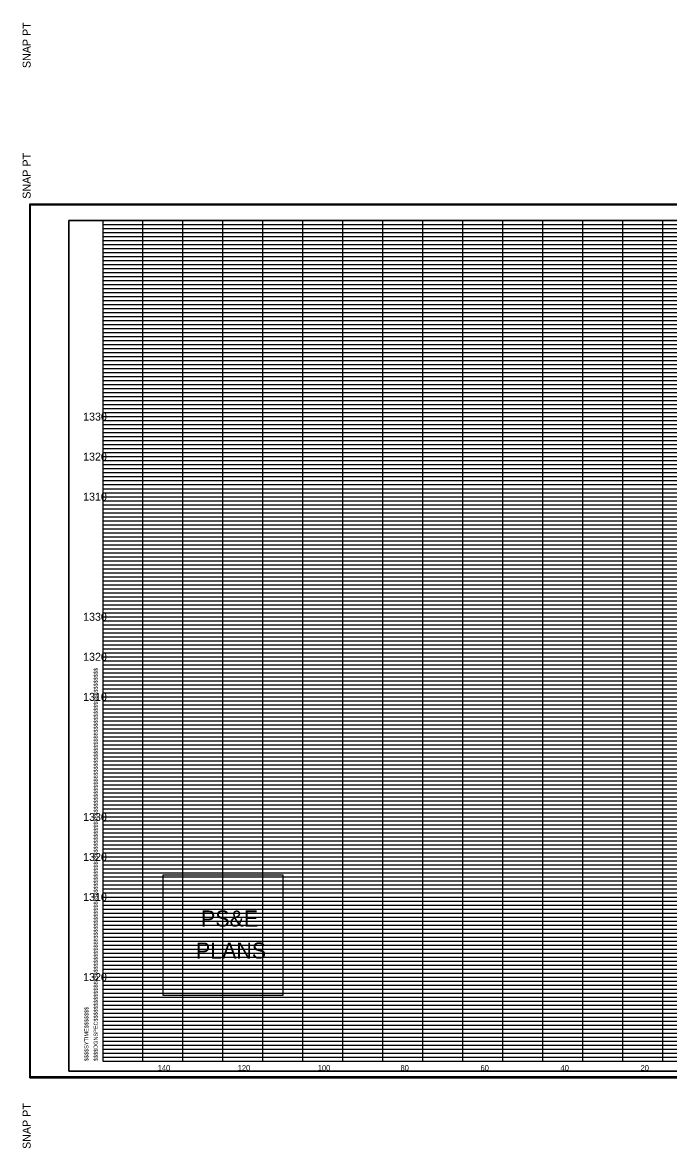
# Model space of a CAD drawing. Extents: x 980 to 1324, y 978 to 1767.
# Drawn here: x 979.9 to 1141.4, y 978.2 to 1259.4 of the extents above; entities that cross this region are included whole.
import ezdxf

# ---------------------------------------------------------------- set-up
doc = ezdxf.new("R2010")
doc.units = 0
for name, color, linetype in [('DESIGN - SHEET - Corner Text', 7, 'Continuous'), ('DESIGN - SHEET - Light Grid', 7, 'Continuous'), ('DESIGN - SHEET - Linework', 7, 'Continuous'), ('DESIGN - SHEET - Plot Shape', 7, 'Continuous'), ('DESIGN - TYPICAL - Text', 7, 'Continuous')]:
    doc.layers.add(name, color=color, linetype=linetype)

# ---------------------------------------------------------------- blocks, each defined once
blk = doc.blocks.new('XSTSHT')
at = {"layer": 'DESIGN - SHEET - Light Grid'}
for p, q in [((0, 20.9), (8, 20.9)), ((8, 20.9), (16, 20.9)), ((0, 20.8), (8, 20.8)), ((0, 20.7), (8, 20.7)), ((0, 20.6), (8, 20.6)), ((8, 20.8), (16, 20.8)), ((8, 20.7), (16, 20.7)), ((8, 20.6), (16, 20.6)), ((0, 20.5), (8, 20.5)), ((0, 20.4), (8, 20.4)), ((0, 20.3), (8, 20.3)), ((8, 20.5), (16, 20.5)), ((8, 20.4), (16, 20.4)), ((8, 20.3), (16, 20.3)), ((0, 20.2), (8, 20.2)), ((0, 20.1), (8, 20.1)), ((8, 20.2), (16, 20.2)), ((8, 20.1), (16, 20.1)), ((0, 19.9), (8, 19.9)), ((0, 19.8), (8, 19.8)), ((0, 19.7), (8, 19.7)), ((8, 19.9), (16, 19.9)), ((8, 19.8), (16, 19.8)), ((8, 19.7), (16, 19.7)), ((0, 19.6), (8, 19.6)), ((0, 19.5), (8, 19.5)), ((8, 19.6), (16, 19.6)), ((8, 19.5), (16, 19.5)), ((0, 19.4), (8, 19.4)), ((0, 19.3), (8, 19.3)), ((0, 19.2), (8, 19.2)), ((8, 19.4), (16, 19.4)), ((8, 19.3), (16, 19.3)), ((8, 19.2), (16, 19.2)), ((0, 19.1), (8, 19.1)), ((0, 18.9), (8, 18.9)), ((8, 19.1), (16, 19.1)), ((8, 18.9), (16, 18.9)), ((0, 18.8), (8, 18.8)), ((0, 18.7), (8, 18.7)), ((0, 18.6), (8, 18.6)), ((8, 18.8), (16, 18.8)), ((8, 18.7), (16, 18.7)), ((8, 18.6), (16, 18.6)), ((0, 18.5), (8, 18.5)), ((0, 18.4), (8, 18.4)), ((0, 18.3), (8, 18.3)), ((8, 18.5), (16, 18.5)), ((8, 18.4), (16, 18.4)), ((8, 18.3), (16, 18.3)), ((0, 18.2), (8, 18.2)), ((0, 18.1), (8, 18.1)), ((8, 18.2), (16, 18.2)), ((8, 18.1), (16, 18.1)), ((0, 17.9), (8, 17.9)), ((0, 17.8), (8, 17.8)), ((8, 17.9), (16, 17.9)), ((8, 17.8), (16, 17.8)), ((0, 17.7), (8, 17.7)), ((0, 17.6), (8, 17.6)), ((0, 17.5), (8, 17.5)), ((8, 17.7), (16, 17.7)), ((8, 17.6), (16, 17.6)), ((8, 17.5), (16, 17.5)), ((0, 17.4), (8, 17.4)), ((0, 17.3), (8, 17.3)), ((0, 17.2), (8, 17.2)), ((8, 17.4), (16, 17.4)), ((8, 17.3), (16, 17.3)), ((8, 17.2), (16, 17.2)), ((0, 17.1), (8, 17.1)), ((0, 16.9), (8, 16.9)), ((8, 17.1), (16, 17.1)), ((8, 16.9), (16, 16.9)), ((0, 16.8), (8, 16.8)), ((0, 16.7), (8, 16.7)), ((0, 16.6), (8, 16.6)), ((8, 16.8), (16, 16.8)), ((8, 16.7), (16, 16.7)), ((8, 16.6), (16, 16.6)), ((0, 16.5), (8, 16.5)), ((0, 16.4), (8, 16.4)), ((8, 16.5), (16, 16.5)), ((8, 16.4), (16, 16.4)), ((0, 16.3), (8, 16.3)), ((0, 16.2), (8, 16.2)), ((0, 16.1), (8, 16.1)), ((8, 16.3), (16, 16.3)), ((8, 16.2), (16, 16.2)), ((8, 16.1), (16, 16.1)), ((0, 15.9), (8, 15.9)), ((0, 15.8), (8, 15.8)), ((8, 15.9), (16, 15.9)), ((8, 15.8), (16, 15.8)), ((0, 15.7), (8, 15.7)), ((0, 15.6), (8, 15.6)), ((0, 15.5), (8, 15.5)), ((8, 15.7), (16, 15.7)), ((8, 15.6), (16, 15.6)), ((8, 15.5), (16, 15.5)), ((0, 15.4), (8, 15.4)), ((0, 15.3), (8, 15.3)), ((0, 15.2), (8, 15.2)), ((8, 15.4), (16, 15.4)), ((8, 15.3), (16, 15.3)), ((8, 15.2), (16, 15.2)), ((0, 15.1), (8, 15.1)), ((8, 15.1), (16, 15.1)), ((0, 14.9), (8, 14.9)), ((0, 14.8), (8, 14.8)), ((0, 14.7), (8, 14.7)), ((8, 14.9), (16, 14.9)), ((8, 14.8), (16, 14.8)), ((8, 14.7), (16, 14.7)), ((0, 14.6), (8, 14.6)), ((0, 14.5), (8, 14.5)), ((0, 14.4), (8, 14.4)), ((8, 14.6), (16, 14.6)), ((8, 14.5), (16, 14.5)), ((8, 14.4), (16, 14.4)), ((0, 14.3), (8, 14.3)), ((0, 14.2), (8, 14.2)), ((0, 14.1), (8, 14.1)), ((8, 14.3), (16, 14.3)), ((8, 14.2), (16, 14.2)), ((8, 14.1), (16, 14.1)), ((0, 13.9), (8, 13.9)), ((0, 13.8), (8, 13.8)), ((8, 13.9), (16, 13.9)), ((8, 13.8), (16, 13.8)), ((0, 13.7), (8, 13.7)), ((0, 13.6), (8, 13.6)), ((8, 13.7), (16, 13.7)), ((8, 13.6), (16, 13.6)), ((0, 13.5), (8, 13.5)), ((0, 13.4), (8, 13.4)), ((0, 13.3), (8, 13.3)), ((8, 13.5), (16, 13.5)), ((8, 13.4), (16, 13.4)), ((8, 13.3), (16, 13.3)), ((0, 13.2), (8, 13.2)), ((0, 13.1), (8, 13.1)), ((8, 13.2), (16, 13.2)), ((8, 13.1), (16, 13.1)), ((0, 12.9), (8, 12.9)), ((0, 12.8), (8, 12.8)), ((0, 12.7), (8, 12.7)), ((8, 12.9), (16, 12.9)), ((8, 12.8), (16, 12.8)), ((8, 12.7), (16, 12.7)), ((0, 12.6), (8, 12.6)), ((0, 12.5), (8, 12.5)), ((0, 12.4), (8, 12.4)), ((8, 12.6), (16, 12.6)), ((8, 12.5), (16, 12.5)), ((8, 12.4), (16, 12.4)), ((0, 12.3), (8, 12.3)), ((0, 12.2), (8, 12.2)), ((0, 12.1), (8, 12.1)), ((8, 12.3), (16, 12.3)), ((8, 12.2), (16, 12.2)), ((8, 12.1), (16, 12.1)), ((0, 11.9), (8, 11.9)), ((8, 11.9), (16, 11.9)), ((0, 11.8), (8, 11.8)), ((0, 11.7), (8, 11.7)), ((0, 11.6), (8, 11.6)), ((8, 11.8), (16, 11.8)), ((8, 11.7), (16, 11.7)), ((8, 11.6), (16, 11.6)), ((0, 11.5), (8, 11.5)), ((0, 11.4), (8, 11.4)), ((0, 11.3), (8, 11.3)), ((8, 11.5), (16, 11.5)), ((8, 11.4), (16, 11.4)), ((8, 11.3), (16, 11.3)), ((0, 11.2), (8, 11.2)), ((0, 11.1), (8, 11.1)), ((8, 11.2), (16, 11.2)), ((8, 11.1), (16, 11.1)), ((0, 10.9), (8, 10.9)), ((0, 10.8), (8, 10.8)), ((0, 10.7), (8, 10.7)), ((8, 10.9), (16, 10.9)), ((8, 10.8), (16, 10.8)), ((8, 10.7), (16, 10.7)), ((0, 10.6), (8, 10.6)), ((0, 10.5), (8, 10.5)), ((8, 10.6), (16, 10.6)), ((8, 10.5), (16, 10.5)), ((0, 10.4), (8, 10.4)), ((0, 10.3), (8, 10.3)), ((0, 10.2), (8, 10.2)), ((8, 10.4), (16, 10.4)), ((8, 10.3), (16, 10.3)), ((8, 10.2), (16, 10.2)), ((0, 10.1), (8, 10.1)), ((0, 9.9), (8, 9.9)), ((8, 10.1), (16, 10.1)), ((8, 9.9), (16, 9.9)), ((0, 9.8), (8, 9.8)), ((0, 9.7), (8, 9.7)), ((0, 9.6), (8, 9.6)), ((8, 9.8), (16, 9.8)), ((8, 9.7), (16, 9.7)), ((8, 9.6), (16, 9.6)), ((0, 9.5), (8, 9.5)), ((0, 9.4), (8, 9.4)), ((0, 9.3), (8, 9.3)), ((8, 9.5), (16, 9.5)), ((8, 9.4), (16, 9.4)), ((8, 9.3), (16, 9.3)), ((0, 9.2), (8, 9.2)), ((0, 9.1), (8, 9.1)), ((8, 9.2), (16, 9.2)), ((8, 9.1), (16, 9.1)), ((0, 8.9), (8, 8.9)), ((0, 8.8), (8, 8.8)), ((8, 8.9), (16, 8.9)), ((8, 8.8), (16, 8.8)), ((0, 8.7), (8, 8.7)), ((0, 8.6), (8, 8.6)), ((0, 8.5), (8, 8.5)), ((8, 8.7), (16, 8.7)), ((8, 8.6), (16, 8.6)), ((8, 8.5), (16, 8.5)), ((0, 8.4), (8, 8.4)), ((0, 8.3), (8, 8.3)), ((0, 8.2), (8, 8.2)), ((8, 8.4), (16, 8.4)), ((8, 8.3), (16, 8.3)), ((8, 8.2), (16, 8.2)), ((0, 8.1), (8, 8.1)), ((0, 7.9), (8, 7.9)), ((8, 8.1), (16, 8.1)), ((8, 7.9), (16, 7.9)), ((0, 7.8), (8, 7.8)), ((0, 7.7), (8, 7.7)), ((0, 7.6), (8, 7.6)), ((8, 7.8), (16, 7.8)), ((8, 7.7), (16, 7.7)), ((8, 7.6), (16, 7.6)), ((0, 7.5), (8, 7.5)), ((0, 7.4), (8, 7.4)), ((8, 7.5), (16, 7.5)), ((8, 7.4), (16, 7.4)), ((0, 7.3), (8, 7.3)), ((0, 7.2), (8, 7.2)), ((0, 7.1), (8, 7.1)), ((8, 7.3), (16, 7.3)), ((8, 7.2), (16, 7.2)), ((8, 7.1), (16, 7.1)), ((0, 6.9), (8, 6.9)), ((0, 6.8), (8, 6.8)), ((8, 6.9), (16, 6.9)), ((8, 6.8), (16, 6.8)), ((0, 6.7), (8, 6.7)), ((0, 6.6), (8, 6.6)), ((0, 6.5), (8, 6.5)), ((8, 6.7), (16, 6.7)), ((8, 6.6), (16, 6.6)), ((8, 6.5), (16, 6.5)), ((0, 6.4), (8, 6.4)), ((0, 6.3), (8, 6.3)), ((0, 6.2), (8, 6.2)), ((8, 6.4), (16, 6.4)), ((8, 6.3), (16, 6.3)), ((8, 6.2), (16, 6.2)), ((0, 6.1), (8, 6.1)), ((8, 6.1), (16, 6.1)), ((0, 5.9), (8, 5.9)), ((0, 5.8), (8, 5.8)), ((0, 5.7), (8, 5.7)), ((8, 5.9), (16, 5.9)), ((8, 5.8), (16, 5.8)), ((8, 5.7), (16, 5.7)), ((0, 5.6), (8, 5.6)), ((0, 5.5), (8, 5.5)), ((0, 5.4), (8, 5.4)), ((8, 5.6), (16, 5.6)), ((8, 5.5), (16, 5.5)), ((8, 5.4), (16, 5.4)), ((0, 5.3), (8, 5.3)), ((0, 5.2), (8, 5.2)), ((0, 5.1), (8, 5.1)), ((8, 5.3), (16, 5.3)), ((8, 5.2), (16, 5.2)), ((8, 5.1), (16, 5.1)), ((0, 4.9), (8, 4.9)), ((0, 4.8), (8, 4.8)), ((8, 4.9), (16, 4.9)), ((8, 4.8), (16, 4.8)), ((0, 4.7), (8, 4.7)), ((0, 4.6), (8, 4.6)), ((8, 4.7), (16, 4.7)), ((8, 4.6), (16, 4.6)), ((0, 4.5), (8, 4.5)), ((0, 4.4), (8, 4.4)), ((0, 4.3), (8, 4.3)), ((8, 4.5), (16, 4.5)), ((8, 4.4), (16, 4.4)), ((8, 4.3), (16, 4.3)), ((0, 4.2), (8, 4.2)), ((0, 4.1), (8, 4.1)), ((8, 4.2), (16, 4.2)), ((8, 4.1), (16, 4.1)), ((0, 3.9), (8, 3.9)), ((0, 3.8), (8, 3.8)), ((0, 3.7), (8, 3.7)), ((8, 3.9), (16, 3.9)), ((8, 3.8), (16, 3.8)), ((8, 3.7), (16, 3.7)), ((0, 3.6), (8, 3.6)), ((0, 3.5), (8, 3.5)), ((0, 3.4), (8, 3.4)), ((8, 3.6), (16, 3.6)), ((8, 3.5), (16, 3.5)), ((8, 3.4), (16, 3.4)), ((0, 3.3), (8, 3.3)), ((0, 3.2), (8, 3.2)), ((0, 3.1), (8, 3.1)), ((8, 3.3), (16, 3.3)), ((8, 3.2), (16, 3.2)), ((8, 3.1), (16, 3.1)), ((0, 2.9), (8, 2.9)), ((8, 2.9), (16, 2.9)), ((0, 2.8), (8, 2.8)), ((0, 2.7), (8, 2.7)), ((0, 2.6), (8, 2.6)), ((8, 2.8), (16, 2.8)), ((8, 2.7), (16, 2.7)), ((8, 2.6), (16, 2.6)), ((0, 2.5), (8, 2.5)), ((0, 2.4), (8, 2.4)), ((0, 2.3), (8, 2.3)), ((8, 2.5), (16, 2.5)), ((8, 2.4), (16, 2.4)), ((8, 2.3), (16, 2.3)), ((0, 2.2), (8, 2.2)), ((0, 2.1), (8, 2.1)), ((8, 2.2), (16, 2.2)), ((8, 2.1), (16, 2.1)), ((0, 1.9), (8, 1.9)), ((0, 1.8), (8, 1.8)), ((0, 1.7), (8, 1.7)), ((8, 1.9), (16, 1.9)), ((8, 1.8), (16, 1.8)), ((8, 1.7), (16, 1.7)), ((0, 1.6), (8, 1.6)), ((0, 1.5), (8, 1.5)), ((8, 1.6), (16, 1.6)), ((8, 1.5), (16, 1.5)), ((0, 1.4), (8, 1.4)), ((0, 1.3), (8, 1.3)), ((0, 1.2), (8, 1.2)), ((8, 1.4), (16, 1.4)), ((8, 1.3), (16, 1.3)), ((8, 1.2), (16, 1.2)), ((0, 1.1), (8, 1.1)), ((0, 0.9), (8, 0.9)), ((8, 1.1), (16, 1.1)), ((8, 0.9), (16, 0.9)), ((0, 0.8), (8, 0.8)), ((0, 0.7), (8, 0.7)), ((0, 0.6), (8, 0.6)), ((8, 0.8), (16, 0.8)), ((8, 0.7), (16, 0.7)), ((8, 0.6), (16, 0.6)), ((0, 0.5), (8, 0.5)), ((0, 0.4), (8, 0.4)), ((0, 0.3), (8, 0.3)), ((8, 0.5), (16, 0.5)), ((8, 0.4), (16, 0.4)), ((8, 0.3), (16, 0.3)), ((0, 0.2), (8, 0.2)), ((0, 0.1), (8, 0.1)), ((8, 0.2), (16, 0.2)), ((8, 0.1), (16, 0.1))]:
    blk.add_line(p, q, dxfattribs=at)
at = {"layer": 'DESIGN - SHEET - Linework'}
for p, q in [((-1.823, -0.414), (-1.823, 21.414)), ((-1.823, 21.414), (32.217, 21.414)), ((1, 0), (1, 21)), ((2, 0), (2, 21)), ((3, 0), (3, 21)), ((4, 0), (4, 21)), ((5, 0), (5, 21)), ((6, 0), (6, 21)), ((7, 0), (7, 21)), ((8, 0), (8, 21)), ((9, 0), (9, 21)), ((10, 0), (10, 21)), ((11, 0), (11, 21)), ((12, 0), (12, 21)), ((13, 0), (13, 21)), ((14, 0), (14, 21)), ((0, 20), (28, 20)), ((0, 19), (32, 19)), ((0, 18), (32, 18)), ((0, 17), (32, 17)), ((0, 16), (32, 16)), ((0, 15), (32, 15)), ((0, 14), (32, 14)), ((0, 13), (32, 13)), ((0, 12), (32, 12)), ((0, 11), (32, 11)), ((0, 10), (32, 10)), ((0, 9), (32, 9)), ((0, 8), (32, 8)), ((0, 7), (32, 7)), ((0, 6), (32, 6)), ((0, 5), (32, 5)), ((0, 4), (32, 4)), ((0, 3), (32, 3)), ((0, 2), (32, 2)), ((0, 1), (32, 1)), ((-1.823, -0.414), (32.217, -0.414))]:
    blk.add_line(p, q, dxfattribs=at)
blk.add_lwpolyline([(0, 21), (0, 0), (32, 0), (32, 21), (0, 21)], dxfattribs=at)
at = {"layer": 'DESIGN - SHEET - Plot Shape'}
for points in [[(-1.803, 21.394), (32.197, 21.394), (32.197, -0.394), (-1.803, -0.394)], [(-0.85, 21), (32, 21), (32, -0.25), (-0.85, -0.25)]]:
    blk.add_lwpolyline(points, close=True, dxfattribs=at)
at = {"layer": 'DESIGN - SHEET - Corner Text'}
for s, height, p in [('  SNAP PT', 0.2, (-1.803, 21.394)), ('$$$$DGNSPEC$$$$$$$$$$$$$$$$$$$$$$$$$$$$$$$$$$$$$$$$$$$$$$$$$$$$$$$$$$$$$$$$$$$$$$$$$$$$$$$$$$$$$$$$$$$$$$$$$$$$$$$$$$$$$$$$$$$', 0.100002, (-0.126, 0)), ('$$$$SYTIME$$$$$$$', 0.1, (-0.358, 0)), ('SNAP PT  ', 0.2, (-1.803, -2.194))]:
    blk.add_text(s, height=height, rotation=90, dxfattribs=at).set_placement(p)

msp = doc.modelspace()

# ---------------------------------------------------------------- linework, layer by layer
at = {"layer": 'DESIGN - SHEET - Corner Text'}
msp.add_lwpolyline([(1015.05, 1046.45), (1015.05, 1016.45), (1045.05, 1016.45), (1045.05, 1046.45)], close=True, dxfattribs=at)
at = {"layer": 'DESIGN - SHEET - Plot Shape'}
msp.add_lwpolyline([(991.5, 997.5), (1320, 997.5), (1320, 1210), (991.5, 1210)], close=True, dxfattribs=at)

# ---------------------------------------------------------------- block references
at = {"layer": 'DESIGN - SHEET - Plot Shape', "xscale": 10, "yscale": 10}
for p in [(1000, 1270), (1000, 1000)]:
    msp.add_blockref('XSTSHT', p, dxfattribs=at)

# ---------------------------------------------------------------- texts
at = {"layer": 'DESIGN - SHEET - Corner Text'}
for s, p in [('PS&E', (1024.57, 1033.63)), ('PLANS', (1023.29, 1025.63))]:
    msp.add_text(s, height=4, dxfattribs=at).set_placement(p)
at = {"layer": 'DESIGN - TYPICAL - Text'}
for s, height, p in [('     1330     ', 2, (991.37, 1160)), ('     1320     ', 2, (991.37, 1150)), ('     1310     ', 2, (991.37, 1140)), ('     1330     ', 2, (991.37, 1110)), ('     1320     ', 2, (991.37, 1100)), ('     1310     ', 2, (991.37, 1090)), ('     1330     ', 2, (991.37, 1060)), ('     1320     ', 2, (991.37, 1050)), ('     1310     ', 2, (991.37, 1040)), ('     1320     ', 2, (991.37, 1020)), ('     140     ', 1.4, (1011.14, 997.6)), ('     120     ', 1.4, (1031.14, 997.6)), ('     100     ', 1.4, (1051.14, 997.6)), ('     80     ', 1.4, (1071.82, 997.6)), ('     60     ', 1.4, (1091.82, 997.6)), ('     40     ', 1.4, (1111.82, 997.6)), ('     20     ', 1.4, (1131.82, 997.6))]:
    msp.add_text(s, height=height, dxfattribs=at).set_placement(p)

doc.saveas('drawing.dxf')
